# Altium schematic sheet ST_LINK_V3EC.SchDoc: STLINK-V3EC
size A3; Date: Not used; ApprovedBy: Not used; CheckedBy: Not used; Author: Not used; CompanyName: STMicroelectronics; DrawnBy: Not used; Engineer: Not used; Organization: Not used; Address1: Not used; Address2: Not used; Address3: Not used; Address4: Not used; DocumentNumber: Not used; Revision: Not used; SheetNumber: 8; SheetTotal: 8
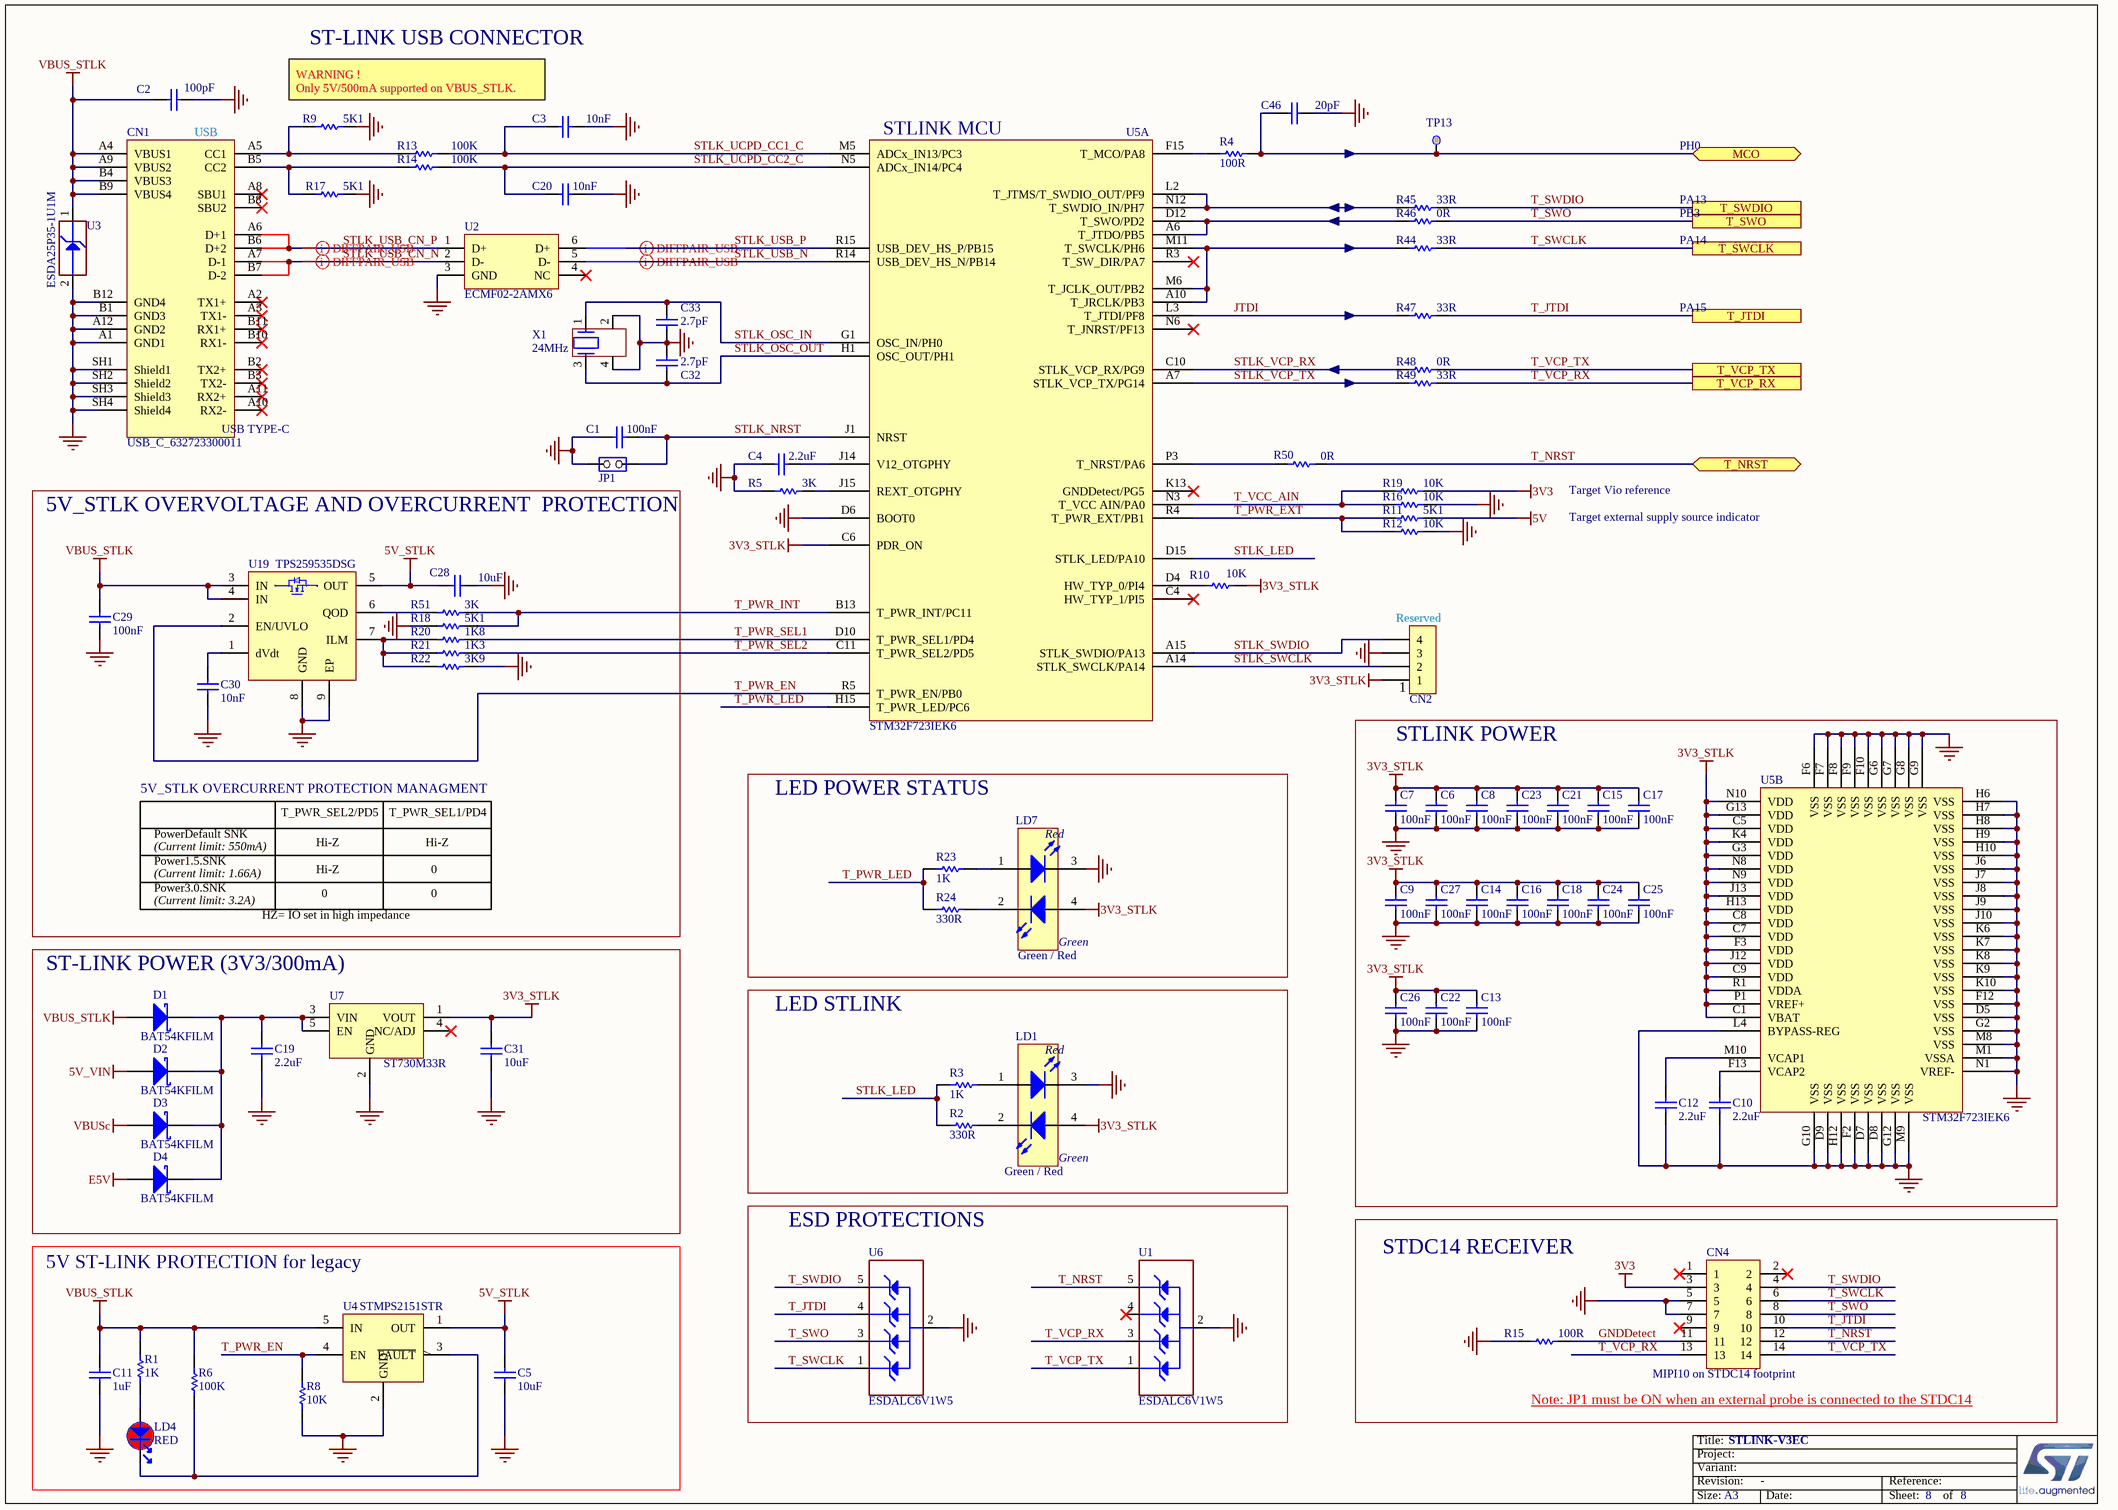
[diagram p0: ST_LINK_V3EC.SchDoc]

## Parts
C1  value 100nF  [C0402]  (hidden comment: Capacitor)
C2  value 100pF  [C0402]  (hidden comment: Capacitor)
C3  value 10nF  [C0402]  (hidden comment: Capacitor)
C4  value 2.2uF  [C0402]  (hidden comment: Capacitor)
C5  value 10uF  [C0603]  (hidden comment: Capacitor)
C6  value 100nF  [C0402]  (hidden comment: Capacitor)
C7  value 100nF  [C0402]  (hidden comment: Capacitor)
C8  value 100nF  [C0402]  (hidden comment: Capacitor)
C9  value 100nF  [C0402]  (hidden comment: Capacitor)
C10  value 2.2uF  [C0402]  (hidden comment: Capacitor)
C11  value 1uF  [C0603]  (hidden comment: Capacitor)
C12  value 2.2uF  [C0402]  (hidden comment: Capacitor)
C13  value 100nF  [C0402]  (hidden comment: Capacitor)
C14  value 100nF  [C0402]  (hidden comment: Capacitor)
C15  value 100nF  [C0402]  (hidden comment: Capacitor)
C16  value 100nF  [C0402]  (hidden comment: Capacitor)
C17  value 100nF  [C0402]  (hidden comment: Capacitor)
C18  value 100nF  [C0402]  (hidden comment: Capacitor)
C19  value 2.2uF  [C0805]  (hidden comment: Capacitor)
C20  value 10nF  [C0402]  (hidden comment: Capacitor)
C21  value 100nF  [C0402]  (hidden comment: Capacitor)
C22  value 100nF  [C0402]  (hidden comment: Capacitor)
C23  value 100nF  [C0402]  (hidden comment: Capacitor)
C24  value 100nF  [C0402]  (hidden comment: Capacitor)
C25  value 100nF  [C0402]  (hidden comment: Capacitor)
C26  value 100nF  [C0402]  (hidden comment: Capacitor)
C27  value 100nF  [C0402]  (hidden comment: Capacitor)
C28  value 10uF  [C0603]  (hidden comment: Capacitor)
C29  value 100nF  [C0402]  (hidden comment: Capacitor)
C30  value 10nF  [C0402]  (hidden comment: Capacitor)
C31  value 10uF  [C0603]  (hidden comment: Capacitor)
C32  value 2.7pF  [C0402]  (hidden comment: Capacitor)
C33  value 2.7pF  [C0402]  (hidden comment: Capacitor)
C46  value 20pF  [C0402]  (hidden comment: Capacitor)
CN1  value USB_C_632723300011  [CON_USB-TYPEC_WE_632723300011]  (hidden comment: USB_TYPE_C_Receptacle)
CN2  Header 4x1  [CON_SAMTEC_TSW-104-07-G-S]  (value not drawn)
CN4  Header 7x2  [CON_STDC14_Receiver_MEDIUM_WITH_MIPI10_3D]  (value not drawn)
D1  value BAT54KFILM  [DIO_SOD523_1A_2K]  (hidden comment: SCHOTTKY_1A_2K)
D2  value BAT54KFILM  [DIO_SOD523_1A_2K]  (hidden comment: SCHOTTKY_1A_2K)
D3  value BAT54KFILM  [DIO_SOD523_1A_2K]  (hidden comment: SCHOTTKY_1A_2K)
D4  value BAT54KFILM  [DIO_SOD523_1A_2K]  (hidden comment: SCHOTTKY_1A_2K)
JP1  Jumper_Header 2x1  [CON_SAMTEC_TSW-102-07-G-S]  (value not drawn)
LD1  value Green / Red  [LED_BI-GR_WE-150141SV73110]  (hidden comment: LED_BICOLOR)
LD4  value RED  [LED_0603_VISHAY_VLMS1300-GS08_RED_1A2K_H0P8]  (hidden comment: LED_red)
LD7  value Green / Red  [LED_BI-GR_WE-150141SV73110]  (hidden comment: LED_BICOLOR)
R1  value 1K  [R0402]  (hidden comment: Resistor)
R2  value 330R  [R0402]  (hidden comment: Resistor)
R3  value 1K  [R0402]  (hidden comment: Resistor)
R4  value 100R  [R0402]  (hidden comment: Resistor)
R5  value 3K  [R0402]  (hidden comment: Resistor)
R6  value 100K  [R0402]  (hidden comment: Resistor)
R8  value 10K  [R0402]  (hidden comment: Resistor)
R9  value 5K1  [R0402]  (hidden comment: Resistor)
R10  value 10K  [R0402]  (hidden comment: Resistor)
R11  value 5K1  [R0402]  (hidden comment: Resistor)
R12  value 10K  [R0402]  (hidden comment: Resistor)
R13  value 100K  [R0402]  (hidden comment: Resistor)
R14  value 100K  [R0402]  (hidden comment: Resistor)
R15  value 100R  [R0402]  (hidden comment: Resistor)
R16  value 10K  [R0402]  (hidden comment: Resistor)
R17  value 5K1  [R0402]  (hidden comment: Resistor)
R18  value 5K1  [R0402]  (hidden comment: Resistor)
R19  value 10K  [R0402]  (hidden comment: Resistor)
R20  value 1K8  [R0402]  (hidden comment: Resistor)
R21  value 1K3  [R0402]  (hidden comment: Resistor)
R22  value 3K9  [R0402]  (hidden comment: Resistor)
R23  value 1K  [R0402]  (hidden comment: Resistor)
R24  value 330R  [R0402]  (hidden comment: Resistor)
R44  value 33R  [R0402]  (hidden comment: Resistor)
R45  value 33R  [R0402]  (hidden comment: Resistor)
R46  value 0R  [R0402]  (hidden comment: Resistor)
R47  value 33R  [R0402]  (hidden comment: Resistor)
R48  value 0R  [R0402]  (hidden comment: Resistor)
R49  value 33R  [R0402]  (hidden comment: Resistor)
R50  value 0R  [R0402]  (hidden comment: Resistor)
R51  value 3K  [R0402]  (hidden comment: Resistor)
TP13  Test Point  [TP_SMD_1MM]  (value not drawn)  (no BOM)
U1  ESDALC6V1W5  [ESD_SOT323-5L]
U2  ECMF02-2AMX6  [ESD_QFN-6L_1P7X1P5_P050]
U3  value ESDA25P35-1U1M  [ESD_QFN1610_2N_1K_2A]  (hidden comment: ESD-TRANSIL)
U4  STMPS2151STR  [MOS_SOT23-5L]
U5  value STM32F723IEK6  [ICC_UFBGA201_176+25_10X10_P065]  (hidden comment: STLINK-V3EC)  (parts A,B of 2)
U6  ESDALC6V1W5  [ESD_SOT323-5L]
U7  ST730M33R  [ICC_SOT23-5L_H1P45]
U19  TPS259535DSG  [ICC_WSON8-EPAD_2X2_P050]
X1  value 24MHz  [CRY_NX2016SA_4P]  (hidden comment: XTAL_4_PINS)

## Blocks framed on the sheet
5V_STLK OVERVOLTAGE AND OVERCURRENT  PROTECTION: C28-C30 R18 R20-R22 R51 U19
LED POWER STATUS: LD7 R23 R24
STLINK POWER: C6-C10 C12-C18 C21-C27 U5
ST-LINK POWER (3V3/300mA): C19 C31 D1-D4 U7
LED STLINK: LD1 R2 R3
ESD PROTECTIONS: U1 U6
5V ST-LINK PROTECTION for legacy: C5 C11 LD4 R1 R6 R8 U4
STDC14 RECEIVER: CN4 R15

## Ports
MCO (bidir), T_JTDI, T_NRST (bidir), T_SWCLK, T_SWDIO, T_SWO, T_VCP_RX, T_VCP_TX

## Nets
3V3: CN4.3 R19.2
3V3_STLK: C6.1 C7.1 C8.1 C9.1 C13.1 C14.1 C15.1 C16.1 C17.1 C18.1 C21.1 C22.1 C23.1 C24.1 C25.1 C26.1 C27.1 C31.2 CN2.1 LD1.4(Green_anode) LD7.4(Green_anode) R10.2 U5.C1(VBAT) U5.C5(VDD) U5.C6(PDR_ON) U5.C7(VDD) U5.C8(VDD) U5.C9(VDD) U5.F3(VDD) U5.G3(VDD) U5.G13(VDD) U5.H13(VDD) U5.J12(VDD) U5.J13(VDD) U5.K4(VDD) U5.N8(VDD) U5.N9(VDD) U5.N10(VDD) U5.P1(VREF+) U5.R1(VDDA) U7.1(VOUT)
5V: R11.2
5V_STLK: C5.2 C28.2 U4.1(OUT) U19.5(OUT)
5V_VIN: D2.1(A)
E5V: D4.1(A)
GND: C1.1 C2.2 C3.2 C4.1 C5.1 C6.2 C7.2 C8.2 C9.2 C10.1 C11.1 C12.1 C13.2 C14.2 C15.2 C16.2 C17.2 C18.2 C19.1 C20.2 C21.2 C22.2 C23.2 C24.2 C25.2 C26.2 C27.2 C28.1 C29.1 C30.1 C31.1 C32.1 C33.1 C46.1 CN1.A1(GND1) CN1.A12(GND2) CN1.B1(GND3) CN1.B12(GND4) CN1.SH1(Shield1) CN1.SH2(Shield2) CN1.SH3(Shield3) CN1.SH4(Shield4) CN2.3 CN4.5 CN4.7 JP1.2(NO) LD1.3(RED_cathode) LD7.3(RED_cathode) R5.2 R8.1 R9.2 R12.2 R15.1 R16.2 R17.2 R18.1 R22.2 U1.2(GND) U2.3(GND) U3.2(GND) U4.2(GND) U5.D5(VSS) U5.D6(BOOT0) U5.D7(VSS) U5.D8(VSS) U5.D9(VSS) U5.F2(VSS) U5.F6(VSS) U5.F7(VSS) U5.F8(VSS) U5.F9(VSS) U5.F10(VSS) U5.F12(VSS) U5.G2(VSS) U5.G6(VSS) U5.G7(VSS) U5.G8(VSS) U5.G9(VSS) U5.G10(VSS) U5.G12(VSS) U5.H6(VSS) U5.H7(VSS) U5.H8(VSS) U5.H9(VSS) U5.H10(VSS) U5.H12(VSS) U5.J6(VSS) U5.J7(VSS) U5.J8(VSS) U5.J9(VSS) U5.J10(VSS) U5.K6(VSS) U5.K7(VSS) U5.K8(VSS) U5.K9(VSS) U5.K10(VSS) U5.L4(BYPASS-REG) U5.M1(VSSA) U5.M8(VSS) U5.M9(VSS) U5.N1(VREF-) U6.2(GND) U7.2(GND) U19.8(GND) U19.9(EP) X1.2 X1.4
VBUS_STLK: C2.1 C11.2 C29.2 CN1.A4(VBUS1) CN1.A9(VBUS2) CN1.B4(VBUS3) CN1.B9(VBUS4) D1.1(A) R1.2 R6.2 U3.1(IO1) U4.5(IN) U19.3(IN) U19.4(IN)
VBUSc: D3.1(A)
GNDDetect: CN4.11 R15.2
JTDI: R47.1 U5.L3(T_JTDI/PF8)
MCO: C46.2 R4.2 TP13.1 ; port MCO
STLK_LED: R2.1 R3.2 U5.D15(STLK_LED/PA10)
STLK_NRST: C1.2 JP1.1(COMMON) U5.J1(NRST)
STLK_OSC_IN: C33.2 U5.G1(OSC_IN/PH0) X1.1
STLK_OSC_OUT: C32.2 U5.H1(OSC_OUT/PH1) X1.3
STLK_SWCLK: CN2.2 U5.A14(STLK_SWCLK/PA14)
STLK_SWDIO: CN2.4 U5.A15(STLK_SWDIO/PA13)
STLK_UCPD_CC1_C: C3.1 R13.2 U5.M5(ADCx_IN13/PC3)
STLK_UCPD_CC2_C: C20.1 R14.2 U5.N5(ADCx_IN14/PC4)
STLK_USB_CN_N: CN1.A7(D-1) CN1.B7(D-2) U2.2(D-)
STLK_USB_CN_P: CN1.A6(D+1) CN1.B6(D+2) U2.1(D+)
STLK_USB_N: U2.5(D-) U5.R14(USB_DEV_HS_N/PB14)
STLK_USB_P: U2.6(D+) U5.R15(USB_DEV_HS_P/PB15)
STLK_VCP_RX: R48.1 U5.C10(STLK_VCP_RX/PG9)
STLK_VCP_TX: R49.1 U5.A7(STLK_VCP_TX/PG14)
T_JTDI: CN4.10 R47.2 U6.4(IO3) ; port T_JTDI
T_NRST: CN4.12 R50.2 U1.5(IO4) ; port T_NRST
T_PWR_EN: R8.2 U4.4(EN) U5.R5(T_PWR_EN/PB0) U19.2(EN/UVLO)
T_PWR_EXT: R11.1 R12.1 U5.R4(T_PWR_EXT/PB1)
T_PWR_INT: R18.2 R51.2 U5.B13(T_PWR_INT/PC11)
T_PWR_LED: R23.2 R24.2 U5.H15(T_PWR_LED/PC6)
T_PWR_SEL1: R20.2 U5.D10(T_PWR_SEL1/PD4)
T_PWR_SEL2: R21.2 U5.C11(T_PWR_SEL2/PD5)
T_SWCLK: CN4.6 R44.2 U6.1(IO1) ; port T_SWCLK
T_SWDIO: CN4.4 R45.2 U6.5(IO4) ; port T_SWDIO
T_SWO: CN4.8 R46.2 U6.3(IO2) ; port T_SWO
T_VCC_AIN: R16.1 R19.1 U5.N3(T_VCC_AIN/PA0)
T_VCP_RX: CN4.13 R49.2 U1.3(IO2) ; port T_VCP_RX
T_VCP_TX: CN4.14 R48.2 U1.1(IO1) ; port T_VCP_TX
NetC4_2: C4.2 U5.J14(V12_OTGPHY)
NetC10_2: C10.2 U5.F13(VCAP2)
NetC12_2: C12.2 U5.M10(VCAP1)
NetC19_2: C19.2 D1.2(K) D2.2(K) D3.2(K) D4.2(K) U7.3(VIN) U7.5(EN)
NetC30_2: C30.2 U19.1(dVdt)
NetCN1_A5: CN1.A5(CC1) R9.1 R13.1
NetCN1_B5: CN1.B5(CC2) R14.1 R17.1
NetLD1_1: LD1.1(Red_anode) R3.1
NetLD1_2: LD1.2(Green_cathode) R2.2
NetLD4_1: LD4.1 R1.1
NetLD4_2: LD4.2 R6.1 U4.3(~{FAULT})
NetLD7_1: LD7.1(Red_anode) R23.1
NetLD7_2: LD7.2(Green_cathode) R24.1
NetR4_1: R4.1 U5.F15(T_MCO/PA8)
NetR5_1: R5.1 U5.J15(REXT_OTGPHY)
NetR10_1: R10.1 U5.D4(HW_TYP_0/PI4)
NetR20_1: R20.1 R21.1 R22.1 U19.7(ILM)
NetR44_1: R44.1 U5.A10(T_JRCLK/PB3) U5.M6(T_JCLK_OUT/PB2) U5.M11(T_SWCLK/PH6)
NetR45_1: R45.1 U5.L2(T_JTMS/T_SWDIO_OUT/PF9) U5.N12(T_SWDIO_IN/PH7)
NetR46_1: R46.1 U5.A6(T_JTDO/PB5) U5.D12(T_SWO/PD2)
NetR50_1: R50.1 U5.P3(T_NRST/PA6)
NetR51_1: R51.1 U19.6(QOD)

Not connected (* = marked no-connect by the designer): CN1 A2(TX1+)* A3(TX1-)* A8(SBU1)* A10(RX2-)* A11(RX2+)* B2(TX2+)* B3(TX2-)* B8(SBU2)* B10(RX1-)* B11(RX1+)*; CN4 1* 2* 9*; U1 4(IO3)*; U2 4(NC)*; U5 C4(HW_TYP_1/PI5)* K13(GNDDetect/PG5)* N6(T_JNRST/PF13)* R3(T_SW_DIR/PA7)*; U7 4(NC/ADJ)*

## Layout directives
differential pair; rule Impedance Constraint [Min = 85.00    Max = 95.00    ]: STLK_USB_CN_N, STLK_USB_CN_P, STLK_USB_N, STLK_USB_P

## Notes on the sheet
- ST-LINK USB CONNECTOR
- WARNING !
  Only 5V/500mA supported on VBUS_STLK.
- (near CN1) USB
- (near U5) STLINK MCU
- PH0
- PA13
- PA14
- PB3
- PA15
- Target Vio reference
- Target external supply source indicator
- (near CN2) Reserved
- (near CN2) 1
- 5V_STLK OVERCURRENT PROTECTION MANAGMENT
- PowerDefault SNK
- (Current limit: 550mA)
- T_PWR_SEL2/PD5
- Hi-Z
- T_PWR_SEL1/PD4
- Power1.5.SNK
- (Current limit: 1.66A)
- Power3.0.SNK
- (Current limit: 3.2A)
- HZ= IO set in high impedance
- 0
- (near CN4) MIPI10 on STDC14 footprint
- Note: JP1 must be ON when an external probe is connected to the STDC14

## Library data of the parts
C1 C6-C9 C13-C18 C21-C27 = MCD-00006: Capacitor, MLCC, 100nF, 16V, X7R, 10%, 0402, T=0.5mm; Manufacturer_Part_Number: CC0402KRX7R7BB104; Manufacturer: YAGEO; Alternate_Manufacturer_Part_Number: GCM155R71C104KA55D; Alternate_Manufacturer: MURATA; Provided_By: SUBCO
C2 = MCD-00205: Capacitor, MLCC, 100pF, 50V, NPO, +/-5%, 0402, T=0.5mm; Part_Preference: Recommended; Manufacturer: YAGEO; Manufacturer_Part_Number: CC0402JRNPO9BN101; Component_Country_Of_Origin: China
C3 C20 = MCD-02198: Capacitor, MLCC, 10nF, 50V, X7R, +/-10%, 0402, T=0.5mm; Part_Preference: Recommended; Manufacturer: YAGEO; Manufacturer_Part_Number: CC0402KRX7R9BB103; Order_Code_RS: 6169644; Component_Country_Of_Origin: China
C4 C10 C12 = MCD-02606: Capacitor, MLCC, 2.2uF, 6.3V, X5R, +/-10%, 0402, T=0.5mm; Part_Preference: Recommended; Manufacturer: YAGEO; Manufacturer_Part_Number: CC0402KRX5R5BB225; Order_Code_RS: 1992205
C5 C28 C31 = MCD-00099: Capacitor, MLCC, 10uF, 10V, X5R, +/-10%, 0603, T=0.8mm; Part_Preference: Recommended; Manufacturer: MURATA; Manufacturer_Part_Number: GRM188R61A106KE69D; Order_Code_RS: 170-6168; Component_Country_Of_Origin: Japan
C11 = MCD-00010: Capacitor, MLCC, 1uF, 16V, X5R, 10%, 0603, T=0,8mm; Manufacturer_Part_Number: CC0603KRX5R7BB105; Manufacturer: YAGEO; Provided_By: SUBCO; Initial_Board_Reference: MB1274; Item Type: Item; Path: ws/MCD_ApplicationBoards/Lists/MCDPARTSdatabase
C19 = MCD-02372: Capacitor, MLCC, 2.2uF, 25V, X7R, +/-10%, 0805, T=1,25mm; Manufacturer_Part_Number: GRM21BR71E225KE11L; Manufacturer: MURATA; Part_Preference: Recommended; ECCN_US: EAR99; ECCN_EU: NEC; Provided_By: SUBCO
C29 = MCD-02355: Capacitor, MLCC, 100nF, 25V, X7R, +/-10%, 0402, T=0.5mm; Part_Preference: Recommended; Manufacturer: WALSIN; Manufacturer_Part_Number: 0402B104K250CT; Order_Code_RS: 176-3114; Component_Country_Of_Origin: Unknown
C30 = MCD-02198: Capacitor, MLCC, 10nF, 50V, X7R, +/-10%, 0402, T=0.5mm; Part_Preference: Recommended; Manufacturer: YAGEO; Manufacturer_Part_Number: CC0402KRX7R9BB103; Order_Code_RS: 6169644; Component_Country_Of_Origin: China; ShowFields: YES; ID: 4298
C32 C33 = MCD-01774: Capacitor, MLCC, 2.7pF, 50V, NPO, +/-0.1pF, 0402, T=0.5mm; Part_Preference: Recommended; Manufacturer: YAGEO; Manufacturer_Part_Number: CC0402BRNPO9BN2R7; Component_Country_Of_Origin: China
C46 = MCD-00016: Capacitor, MLCC, 20pF, 50V, NPO, +/- 5%, 0402, T=0.5mm; Part_Preference: Recommended; Manufacturer: YAGEO; Manufacturer_Part_Number: CC0402JRNPO9BN200; Component_Country_Of_Origin: China; ShowFields: YES; ID: 2479
CN1 = MCD-02273: USB_TypeC, 24pins, RA, TH, T=1.9mm (USB certified); Part_Type: Connector; Part_Preference: Recommended; Manufacturer: WURTH ELEKTRONIK; Manufacturer_Part_Number: 632723300011; Component_Country_Of_Origin: China; ShowFields: YES; ID: 4373
CN2 = MCD-00029: Header, 4x1, 2,54mm, VR, TH, Height 5.84mm/2.54mm; Manufacturer_Part_Number: TSW-104-07-x-S; Manufacturer: SAMTEC; Part_Type: Connector; Provided_By: SUBCO
CN4 = MCD-01226: Header, 5x2, 1.27mm, VR, SMD, T=5.97mm/3.05mm; Part_Type: Connector; Part_Preference: Recommended; Manufacturer: SAMTEC; Manufacturer_Part_Number: FTSH-105-01-L-DV-K; Value: Header 5x2; Order_Code_RS: 159-2332; Component_Country_Of_Origin: China, Costa Rica, Malaysia, United States, Vietnam
D1-D4 = MCD-01677: Small signal Schottky diodes; BMS_Part_Number: 9151123; Part_Type: Diode; Part_Preference: Recommended; Manufacturer: STMICROELECTRONICS; Manufacturer_HQ_COO: EU; Component_Country_Of_Origin: China
JP1 = MCD-00045: Header, 2x1, 2,54mm, VR, TH, Height 5.84mm/2.54mm; Part_Preference: Recommended; Part_Type: Connector; Manufacturer: SAMTEC; Manufacturer_Part_Number: TSW-102-07-G-S; Alternate_Manufacturer: JIUBABA; LIANYI; Alternate_Manufacturer_Part_Number: 313102S111116;313102S111116
LD1 LD7 = MCD-02631: LED Bicolor, Green/Red, 2V, 20mA,  4-PLCC; Part_Type: Display; Part_Preference: Recommended; Manufacturer: WURTH ELEKTRONIK; Manufacturer_Part_Number: 150141SV73110; Order_Code_RS: 184-6963
LD4 = MCD-00587: LED Red, 0603 SMD, 2V Forward Voltage; Part_Type: Display; Manufacturer_Part_Number: VLMS1300-GS08; Manufacturer: VISHAY; Alternate_Manufacturer_Part_Number: LS Q976-NR-1; Alternate_Manufacturer: OSRAM OPTO SEMICONDUCTORS; Provided_By: SUBCO
R1 = MCD-00061: Resistor,1K,0402,1%,1/16W; Manufacturer_Part_Number: RC0402FR-071KL; Manufacturer: YAGEO; Provided_By: SUBCO; Initial_Board_Reference: MB1274; Item Type: Item; Path: ws/MCD_ApplicationBoards/Lists/MCDPARTSdatabase
R2 R24 = MCD-00062: Resistor, 330R, 0402, +/-1%, 1/16W; Part_Preference: Recommended; Manufacturer: YAGEO; Manufacturer_Part_Number: RC0402FR-07330RL; Component_Country_Of_Origin: China
R3 R23 = MCD-02665: Resistor, 1K, 0402, +/-0.1%, 1/16W, +/-25ppm/°C; Part_Preference: Recommended; Manufacturer: YAGEO; Manufacturer_Part_Number: RT0402BRD071KL; Order_Code_RS: 199-1298
R4 = MCD-00119: Resistor, 100R, 0402, +/-1%, 1/16W; Part_Preference: Not recommended; Manufacturer: YAGEO; Manufacturer_Part_Number: RC0402FR-07100RL; Component_Country_Of_Origin: China; ShowFields: YES; ID: 2748
R5 = MCD-00185: Resistor,3K,0402,1%,1/16W; Manufacturer_Part_Number: RC0402FR-073KL; Manufacturer: YAGEO; Provided_By: SUBCO
R6 = MCD-00059: Resistor,100K,0402,1%,1/16W; Manufacturer_Part_Number: RC0402FR-07100KL; Manufacturer: YAGEO; Alternate_Manufacturer_Part_Number: RT0402FRE07100KL; Provided_By: SUBCO; Initial_Board_Reference: MB1274; Item Type: Item; Path: ws/MCD_ApplicationBoards/Lists/MCDPARTSdatabase
R8 = MCD-00053: Resistor,10K,0402,1%,1/16W; Manufacturer_Part_Number: RC0402FR-0710KL; Manufacturer: YAGEO; Provided_By: SUBCO; Initial_Board_Reference: MB1274; Item Type: Item; Path: ws/MCD_ApplicationBoards/Lists/MCDPARTSdatabase
R9 R11 R17 R18 = MCD-00333: Resistor, 5K1, 0402, +/-1%, 1/16W; Part_Preference: Recommended; Manufacturer: YAGEO; Manufacturer_Part_Number: RC0402FR-075K1L
R10 = MCD-00053: Resistor,10K,0402,1%,1/16W; Manufacturer_Part_Number: RC0402FR-0710KL; Manufacturer: YAGEO; Provided_By: SUBCO
R12 R16 R19 = MCD-00053: Resistor, 10K, 0402, +/-1%, 1/16W; BMS_Part_Number: 9131590; Part_Preference: Recommended; Manufacturer: YAGEO; Manufacturer_Part_Number: RC0402FR-0710KL; Component_Country_Of_Origin: China; ShowFields: YES; ID: 2539
R13 R14 = MCD-00059: Resistor, 100K, 0402, +/-1%, 1/16W; Part_Preference: Recommended; Manufacturer: YAGEO; Manufacturer_Part_Number: RC0402FR-07100KL; Component_Country_Of_Origin: China; ShowFields: YES; ID: 2533
R15 = MCD-00119: Resistor, 100R, 0402, +/-1%, 1/16W; Part_Preference: Not recommended; Manufacturer: YAGEO; Manufacturer_Part_Number: RC0402FR-07100RL; Component_Country_Of_Origin: China
R20 = MCD-00409: Resistor, 1K8, 0402, +/-1%, 1/16W; Part_Preference: Recommended; Manufacturer: YAGEO; Manufacturer_Part_Number: RC0402FR-071K8L; Component_Country_Of_Origin: China
R21 = MCD-00381: Resistor, 1K3, 0402, +/-1%, 1/16W; Part_Preference: Recommended; Manufacturer: YAGEO; Manufacturer_Part_Number: RC0402FR-071K3L; Component_Country_Of_Origin: China; ShowFields: YES; ID: 2898
R22 = MCD-02455: Resistor, 3K9, 0402, +/-1%, 1/16W, +/-100ppm/°C; Part_Preference: Recommended; Manufacturer: YAGEO; Manufacturer_Part_Number: RC0402FR-073K9L; Order_Code_RS: 198-7783; Component_Country_Of_Origin: China; ShowFields: YES; ID: 4561
R44 R45 R47 R49 = MCD-00455: Resistor, 33R, 0402, +/-1%, 1/16W; Part_Preference: Recommended; Manufacturer: YAGEO; Manufacturer_Part_Number: RC0402FR-0733RL; Component_Country_Of_Origin: China; ShowFields: YES; ID: 2821
R46 R48 = MCD-00052: Resistor, 0R, 0402, +/-5%, 1/16W; Part_Preference: Recommended; Manufacturer: YAGEO; Manufacturer_Part_Number: RC0402JR-070RL; Order_Code_RS: 618-5804; Component_Country_Of_Origin: China; ShowFields: YES; ID: 2540
R50 = MCD-00052: Resistor, 0R, 0402, +/-5%, 1/16W; Part_Preference: Recommended; Manufacturer: YAGEO; Manufacturer_Part_Number: RC0402JR-070RL; Order_Code_RS: 618-5804; Component_Country_Of_Origin: China
R51 = MCD-00185: Resistor, 3K, 0402, +/-1%, 1/16W; Part_Preference: Recommended; Manufacturer: YAGEO; Manufacturer_Part_Number: RC0402FR-073KL; Component_Country_Of_Origin: China
TP13 = MCD-00074: Test Point 1mm; Part_Type: Mechanical
U1 U6 = MCD-00136: Dual Transil array for ESD protection; BMS_Part_Number: 9151112; Part_Type: Diode; Part_Preference: Recommended; Manufacturer: STMICROELECTRONICS; Manufacturer_HQ_COO: EU; Component_Country_Of_Origin: China
U2 = MCD-00649: Common mode filter with ESD protection for USB 2.0 interface; BMS_Part_Number: 9151138; Part_Type: Diode; Part_Preference: Recommended; Manufacturer: STMICROELECTRONICS; Manufacturer_HQ_COO: EU; Component_Country_Of_Origin: China; ShowFields: YES; ID: 3094
U3 = MCD-01207: High power Transient voltage suppressor:25V/35A EOS and ESD transients protection.; Part_Type: Diode; Manufacturer: STMICROELECTRONICS; BMS_Part_Number: 9179045; ECCN_US: EAR99; ECCN_EU: NEC; Provided_By: SUBCO with ST control
U4 = MCD-00159: 500mA, Enhanced single channel power switches with active high enable pin; Part_Type: IC; Manufacturer: STMICROELECTRONICS; Alternate_Manufacturer_Part_Number: TPS2051C; Alternate_Manufacturer: TEXAS INSTRUMENTS; BMS_Part_Number: 9159009; Provided_By: Subcon; Initial_Board_Reference: MB1264
U5 = MCD-02706: STM32F723IEK  (STM32F7) BGA176; BMS_Part_Number: 9175300; Part_Type: IC; Part_Preference: Recommended; Manufacturer: STMICROELECTRONICS; Order_Code_RS: 135-8241; ShowFields: YES; ID: 4812
U7 = MCD-02514: LDO, 3.3V, 300mA, High input voltage: 2.5V to 28V, SOT23-5L; Part_Type: IC; Part_Preference: Recommended; Manufacturer: STMICROELECTRONICS
U19 = MCD-02532: eFuse with Fast Overvoltage Protection 2.7V to 18V 4A 34mOhm 8-Pin WSON; Part_Type: IC; Part_Preference: Recommended; Manufacturer: TEXAS INSTRUMENTS; Order_Code_RS: NA
X1 = MCD-01036: Crystal, 24MHz, 6pF, +/-20ppm, 80R, 2x1.6mm; BMS_Part_Number: 9157045; Part_Type: Crystal_Osc; Part_Preference: Recommended; Manufacturer: NDK; Manufacturer_Part_Number: NX2016SA-24MHZ-EXS00A-CS10820; Component_Country_Of_Origin: Unknown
